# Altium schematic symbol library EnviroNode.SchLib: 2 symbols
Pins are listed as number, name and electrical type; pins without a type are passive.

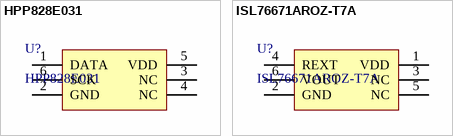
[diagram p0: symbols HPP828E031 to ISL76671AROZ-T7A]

## HPP828E031
designator U?
IC SENSOR TEMP/HUM DGTL; Manufacturer: Measurement Specialties Inc.; Sensor Type: Humidity and Temperature; Humidity Range: 0 ~ 100% RH; Accuracy: ±2% RH; Response Time: 5s; Output: Digital, I²C; Voltage - Supply: 1.5 V ~ 3.6 V
footprint DFN-6
pins: 1 DATA, 2 GND, 3 NC, 4 NC, 5 VDD, 6 SCK

## ISL76671AROZ-T7A
designator U?
IC AMBIENT LIGHT SENSOR; Manufacturer: Intersil; With Proximity Sensor: No; Wavelength: 550nm; Voltage - Supply: 1.8 V ~ 3 V; Output Type: Current
footprint ODFN-6
pins: 1 VDD, 2 GND, 3 NC, 4 REXT, 5 NC, 6 VOUT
